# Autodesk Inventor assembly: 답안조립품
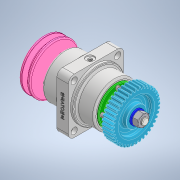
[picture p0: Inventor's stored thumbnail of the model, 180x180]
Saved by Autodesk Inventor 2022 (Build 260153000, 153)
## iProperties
Created: 2023-10
Part Number: 답안조립품
Document SubType Name: Assembly
Designer: PC-13
Author: PC-13
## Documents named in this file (12)
- C:\Users\PC-13\Desktop\731006V1007\답안조립품.iam
- C:\Users\PC-13\Desktop\731006V1007\본체.ipt
- C:\Users\PC-13\Desktop\731006V1007\볼트 M4x0.7.ipt
- C:\Users\PC-13\Desktop\731006V1007\스퍼기어.ipt
- C:\Users\PC-13\Desktop\731006V1007\오일실 20x35x8.ipt
- C:\Users\PC-13\Desktop\731006V1007\와셔 12x24.ipt
- C:\Users\PC-13\Desktop\731006V1007\축.ipt
- C:\Users\PC-13\Desktop\731006V1007\커버.ipt
- C:\Users\PC-13\Desktop\731006V1007\키 5x5.ipt
- C:\Users\PC-13\Desktop\731006V1007\베어링 6204.ipt
- C:\Users\PC-13\Desktop\731006V1007\V벨트풀리.ipt
- C:\Users\PC-13\Desktop\731006V1007\너트 M12x1.25.ipt
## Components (1 placed, 1 different names)
1. V벨트풀리:1
